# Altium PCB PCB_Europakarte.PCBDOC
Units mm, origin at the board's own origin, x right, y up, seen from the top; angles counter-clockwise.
Board outline 160 x 100 mm, 2 copper layers (Top Layer, Bottom Layer), stack 1.521 mm thick; 2 components, 0 nets, 100 pads, 0 vias.
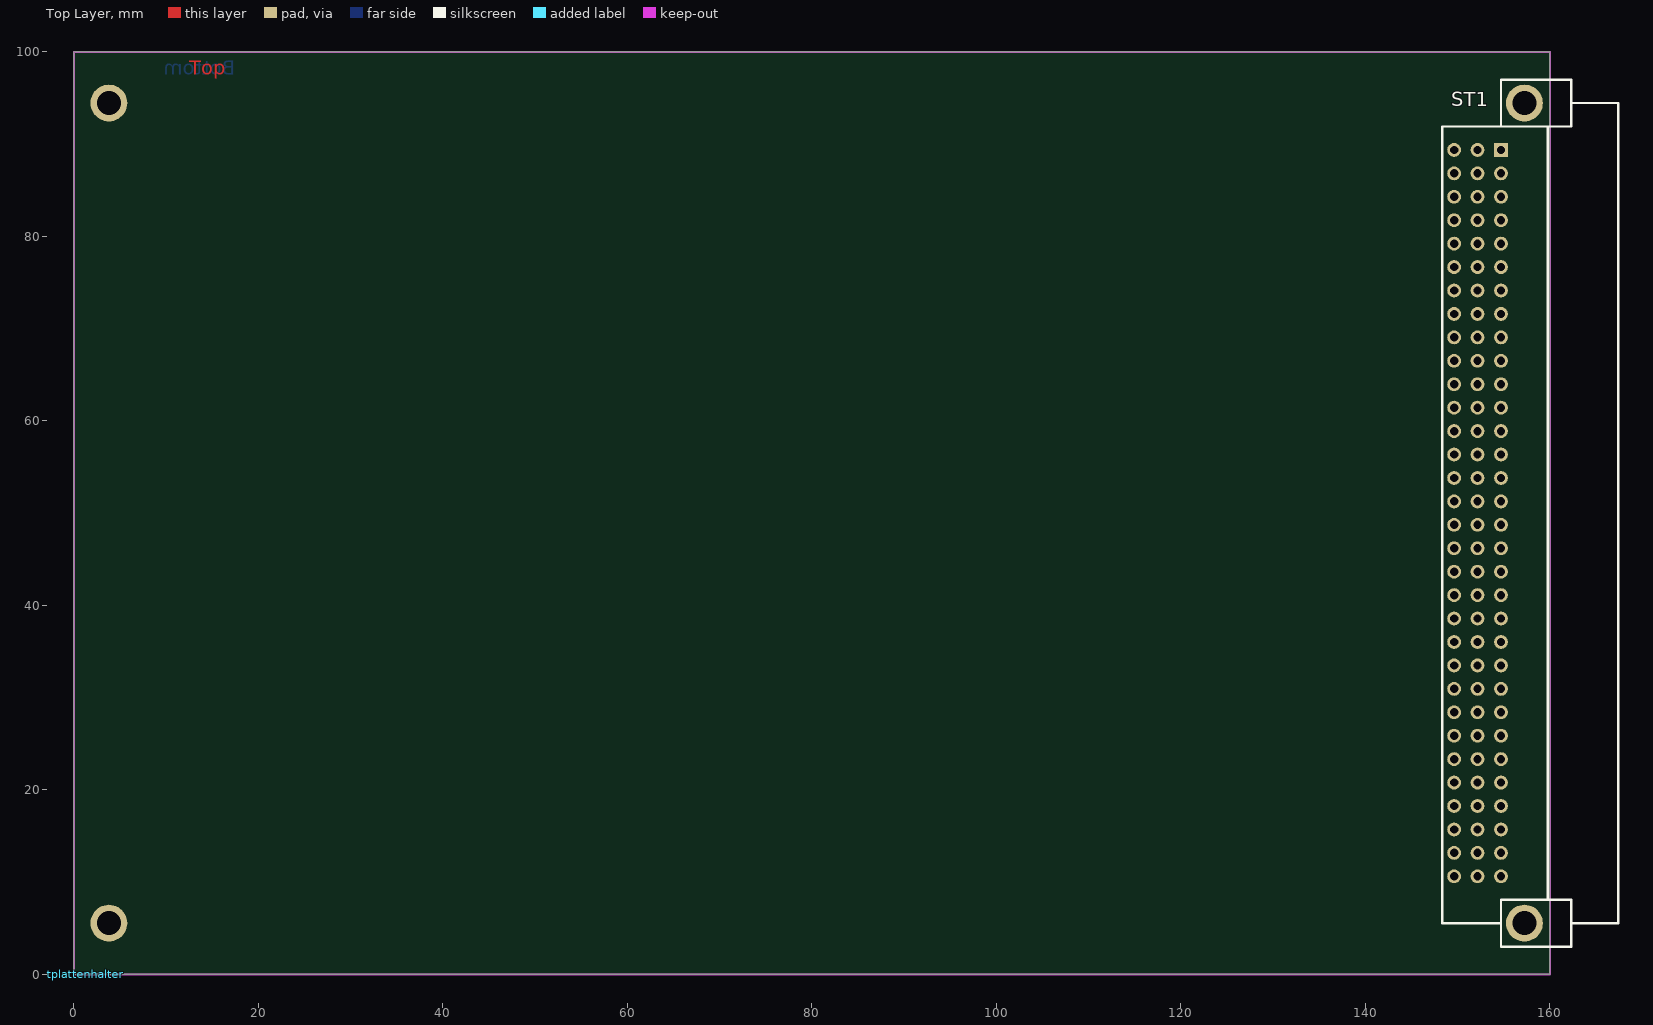
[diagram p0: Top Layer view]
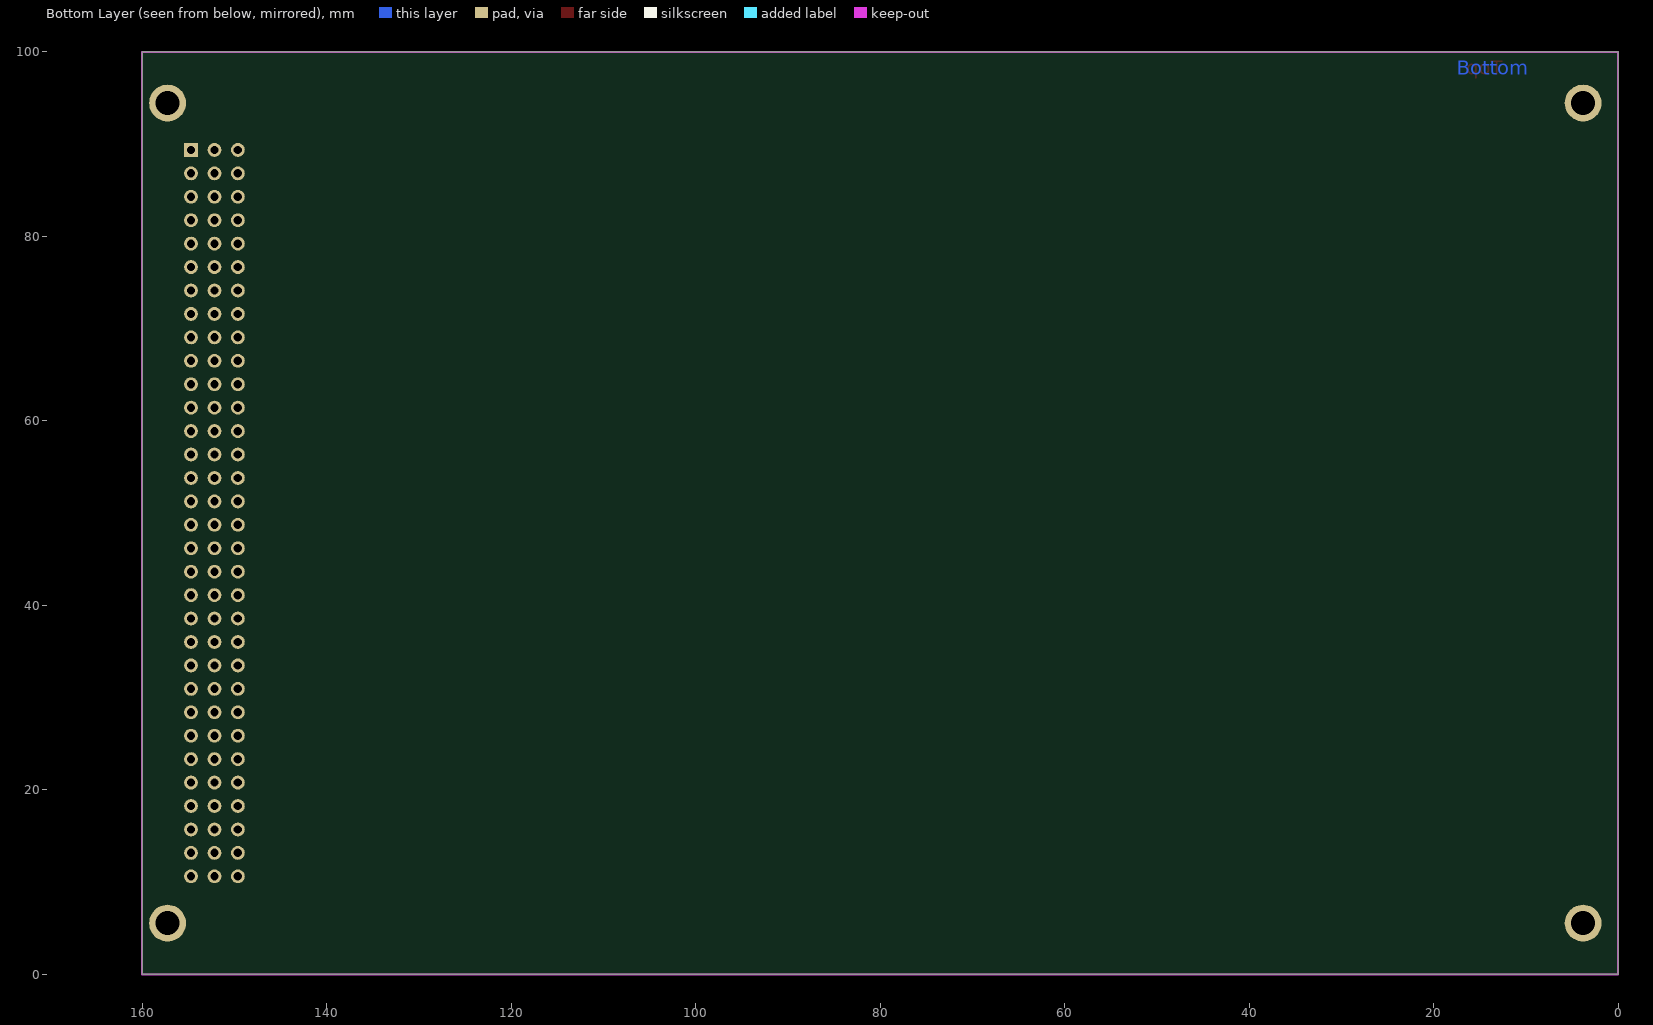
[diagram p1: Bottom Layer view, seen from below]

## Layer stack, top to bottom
Top Layer: signal copper 0.0356
Dielectric: core 1.45, FR-4, Dk 4.8
Bottom Layer: signal copper 0.0356

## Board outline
0,0 0,100 160,100 160,0

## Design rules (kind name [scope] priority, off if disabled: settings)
Clearance Clearance_GND_PolygonPlane [(InPolygon AND InNet('GND'))] p1: gap=0.3
Clearance Clearance_GND_Keepout [InNet('GND') vs OnLayer('Keep-Out Layer')] p2: gap=0.5 // GND nach Keepout
Clearance "Clearance ADUC Pads" [(InComponent('U_Aduc')) vs (InComponent('U_Aduc'))] p3: gap=0.25 // ADUC_Pads
Clearance [All] p4: gap=0.25
ComponentClearance [All] p1: gap=0.25 collisioncheckmode=3 verticalgap=0.25 showdistances=FALSE
DiffPairsRouting [All] p1: maxlimit=0.25 minlimit=0.25 mostfreqgap=0.25 maxuncoupledlength=10
FabricationTestPointUsage TestPointUsage [All] p1: valid=0 allowmultiple=FALSE
FabricationTestpoint Testpoint [All] p1: side=3 testpointundercomponent=TRUE minsize=1.016 maxsize=2.54 preferedsize=1.524 minholesize=0 maxholesize=1.016 preferedholesize=0.813 testpointgrid=0.025 allowsidetop=TRUE allowsidebottom=TRUE usegrid=TRUE gridtolerance=0
Height [All] p1: minheight=0 maxheight=60 prefheight=12
HoleSize [All] p1: absolutevalues=TRUE maxlimit=20 minlimit=0.3 maxpercent=80.000 minpercent=20.000
HoleToHoleClearance [All] p1: gap=0.3 allowstackedmicrovias=TRUE
MinimumAnnularRing [All] p1: minimumring=0.15
MinimumSolderMaskSliver [All] p1: minsoldermaskwidth=0.1
NetAntennae [All] p1: netantennaetolerance=0.5
PlaneClearance [All] p1: clearance=0.25
PlaneConnect [All] p1: planeconnectstyle=Relief reliefexpansion=0.5 reliefentries=4 reliefconductorwidth=0.25 reliefairgap=0.25
PolygonConnect PolygonConnect_VIA [isvia] p1: connectstyle=Direct reliefconductorwidth=0.254 reliefentries=4 polygonreliefangle="90 Angle" airgapwidth=0.254
PolygonConnect [All] p2: connectstyle=Relief reliefconductorwidth=0.3 reliefentries=4 polygonreliefangle="90 Angle" airgapwidth=0.25
RoutingCorners [All] p1: cornerstyle=45-Degree minsetback=2 maxsetback=10
RoutingVias [All] p1: holewidth=0.4 width=0.8 viastyle="Through Hole" minholewidth=0.3 minwidth=0.6 maxholewidth=3 maxwidth=6
SilkToSilkClearance [All] p1: silktosilkclearance=0
SilkToSolderMaskClearance SilkscreenOverComponentPads [IsPad] p1: minsilkscreentomaskgap=0.15 clearancetoexposedcopper=TRUE
SolderMaskExpansion [All] p1: expansion=0.05
Width [All] p1: maxlimit=10 minlimit=0.25 preferedwidth=0.3
14 further rules are at their usual default settings.

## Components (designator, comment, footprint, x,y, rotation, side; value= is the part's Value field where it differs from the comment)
Frontplattenhalter "Knürr 2.300.041.9" "MISC_Frontplattenhalter Knürr 2.300.041.9" 0,0 r0 top
ST1 "Comment" CON_VG96_ABC 153.43,50 r270 top

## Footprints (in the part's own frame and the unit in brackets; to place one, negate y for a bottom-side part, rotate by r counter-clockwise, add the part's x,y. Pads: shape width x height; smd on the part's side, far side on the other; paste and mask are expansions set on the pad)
CON_VG96_ABC [mm] "Steckerleiste; DIN 41612; gewinkelt 96pol Nummerierung 1..32+A,B,C"
  round 4 hole 2.6: 0(-44.45,3.81) 0(44.45,3.81)
  rect 1.5x1.5 hole 0.9: 1A(-39.37,1.27)
  round 1.5 hole 0.9: 1B(-39.37,-1.27) 1C(-39.37,-3.81) 2A(-36.83,1.27) 2B(-36.83,-1.27) 2C(-36.83,-3.81) 3A(-34.29,1.27) 3B(-34.29,-1.27) 3C(-34.29,-3.81) 4A(-31.75,1.27) 4B(-31.75,-1.27) 4C(-31.75,-3.81) 5A(-29.21,1.27) 5B(-29.21,-1.27) 5C(-29.21,-3.81) 6A(-26.67,1.27) 6B(-26.67,-1.27) 6C(-26.67,-3.81) 7A(-24.13,1.27) 7B(-24.13,-1.27) 7C(-24.13,-3.81) 8A(-21.59,1.27) 8B(-21.59,-1.27) 8C(-21.59,-3.81) 9A(-19.05,1.27) 9B(-19.05,-1.27) 9C(-19.05,-3.81) 10A(-16.51,1.27) 10B(-16.51,-1.27) 10C(-16.51,-3.81) 11A(-13.97,1.27) 11B(-13.97,-1.27) 11C(-13.97,-3.81) 12A(-11.43,1.27) 12B(-11.43,-1.27) 12C(-11.43,-3.81) 13A(-8.89,1.27) 13B(-8.89,-1.27) 13C(-8.89,-3.81) 14A(-6.35,1.27) 14B(-6.35,-1.27) 14C(-6.35,-3.81) 15A(-3.81,1.27) 15B(-3.81,-1.27) 15C(-3.81,-3.81) 16A(-1.27,1.27) 16B(-1.27,-1.27) 16C(-1.27,-3.81) 17A(1.27,1.27) 17B(1.27,-1.27) 17C(1.27,-3.81) 18A(3.81,1.27) 18B(3.81,-1.27) 18C(3.81,-3.81) 19A(6.35,1.27) 19B(6.35,-1.27) 19C(6.35,-3.81) 20A(8.89,1.27) 20B(8.89,-1.27) 20C(8.89,-3.81) 21A(11.43,1.27) 21B(11.43,-1.27) 21C(11.43,-3.81) 22A(13.97,1.27) 22B(13.97,-1.27) 22C(13.97,-3.81) 23A(16.51,1.27) 23B(16.51,-1.27) 23C(16.51,-3.81) 24A(19.05,1.27) 24B(19.05,-1.27) 24C(19.05,-3.81) 25A(21.59,1.27) 25B(21.59,-1.27) 25C(21.59,-3.81) 26A(24.13,1.27) 26B(24.13,-1.27) 26C(24.13,-3.81) 27A(26.67,1.27) 27B(26.67,-1.27) 27C(26.67,-3.81) 28A(29.21,1.27) 28B(29.21,-1.27) 28C(29.21,-3.81) 29A(31.75,1.27) 29B(31.75,-1.27) 29C(31.75,-3.81) 30A(34.29,1.27) 30B(34.29,-1.27) 30C(34.29,-3.81) 31A(36.83,1.27) 31B(36.83,-1.27) 31C(36.83,-3.81) 32A(39.37,1.27) 32B(39.37,-1.27) 32C(39.37,-3.81)
  silkscreen extent -46.99,-5.08 46.99,13.97, body extent -47,-4.11 47,13.89, height 9.5
"MISC_Frontplattenhalter Knürr 2.300.041.9" [mm] "Knürr Frontplattenhalter"
  body extent -2.2,-3.5 6.8,103.5, height 8.1

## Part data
ST1: library part CON_VG96-V1

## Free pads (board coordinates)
  round 4 hole 2.6: 1(3.8,5.55) 2(3.8,94.45)

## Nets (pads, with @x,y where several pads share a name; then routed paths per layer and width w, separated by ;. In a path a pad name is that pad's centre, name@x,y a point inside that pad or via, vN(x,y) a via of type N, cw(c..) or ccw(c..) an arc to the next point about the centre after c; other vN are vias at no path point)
pads on no net: ST1.0 ST1.1A ST1.1B ST1.1C ST1.2A ST1.2B ST1.2C ST1.3A ST1.3B ST1.3C ST1.4A ST1.4B ST1.4C ST1.5A ST1.5B ST1.5C ST1.6A ST1.6B ST1.6C ST1.7A ST1.7B ST1.7C ST1.8A ST1.8B ST1.8C ST1.9A ST1.9B ST1.9C ST1.10A ST1.10B ST1.10C ST1.11A ST1.11B ST1.11C ST1.12A ST1.12B ST1.12C ST1.13A ST1.13B ST1.13C ST1.14A ST1.14B ST1.14C ST1.15A ST1.15B ST1.15C ST1.16A ST1.16B ST1.16C ST1.17A ST1.17B ST1.17C ST1.18A ST1.18B ST1.18C ST1.19A ST1.19B ST1.19C ST1.20A ST1.20B ST1.20C ST1.21A ST1.21B ST1.21C ST1.22A ST1.22B ST1.22C ST1.23A ST1.23B ST1.23C ST1.24A ST1.24B ST1.24C ST1.25A ST1.25B ST1.25C ST1.26A ST1.26B ST1.26C ST1.27A ST1.27B ST1.27C ST1.28A ST1.28B ST1.28C ST1.29A ST1.29B ST1.29C ST1.30A ST1.30B ST1.30C ST1.31A ST1.31B ST1.31C ST1.32A ST1.32B ST1.32C

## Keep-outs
Keep-Out Layer:
  the board outline again, w0.2

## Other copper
Top Layer:
  text "Top" at 12.5,97.5 h1.52
Bottom Layer:
  text "Bottom" at 17.5,97.5 h1.52

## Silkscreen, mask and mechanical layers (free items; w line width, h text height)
Board Outline:
  the board outline again, w0.2
Milling Contour (2mm):
  lines w2: -1,-1 161,-1 161,101 -1,101 -1,-1
Contours, Housing:
  lines w0.05: -4.6,0.5 0,0.5 ; -4.6,99.5 0,99.5
  lines w0.1: -4.6,0.25 0,0.25 ; -4.6,0.75 0,0.75 ; -4.6,99.25 0,99.25 ; -4.6,99.75 0,99.75 ; -2.2,-3.5 3.575,-3.5 ; -2.2,8.5 7.3,8.5 7.3,2.1 3.575,2.1 3.575,-3.475 ; -2.2,91.5 7.3,91.5 7.3,97.9 3.575,97.9 3.575,103.475 ; -2.2,103.5 3.575,103.5 ; -1.95,112.85 1.975,114.975 ; -0.7,103.8 2.475,105.925 ; -4.6,-14.2 -2.2,-14.2 -2.2,114.2 -4.6,114.2 -4.6,-14.2
  text "Frontplatte (d=2.4mm)" at 2.825,114.2 h1.52
  text "(Standoff Height -4.3mm)" at 2.825,111.7 h1.52
  text "(Overall Height = 6TE = 30.48mm)" at 2.825,108.7 h1.52
  text "Leiterplattenhalter" at 2.8,105.375 h1.52

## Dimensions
0,100 to 160,100 on Dimensions
0,100 to 0,0 on Dimensions
-4.6,114.2 to -4.6,-14.2 on Dimensions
